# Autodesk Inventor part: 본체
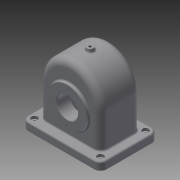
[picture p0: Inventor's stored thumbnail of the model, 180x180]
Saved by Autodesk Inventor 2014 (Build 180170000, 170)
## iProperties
Created: 2016-10
Part Number: 본체
Material: 일반
Document SubType Name: Modeling
Designer: USER
Density: 1 g/cm^3
Appearance: 기본값
Author: USER
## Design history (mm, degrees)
sketch "스케치1"
  geometry: L1 (0, 0)-(0, 15); L2 (0, 15)-(-150, 15); L3 (-150, 15)-(-150, 0); L4 (-150, 0)-(0, 0)
  constraints: 8 end point, 2 parallel, 1 perpendicular, 1 vertical
  dimensions: "d0" = 15 distance of L1.start L1.end; "d1" = 150 distance of L1.end L2.end
extrude "돌출1" new body sketch "스케치1" stored distance "d2" = 110; taper "d3" = 0 deg
sketch "스케치2"
  geometry: L1 (0, 0)-(-150, 0) reference; L2 (-150, 0)-(-150, 15) reference; L3 (-150, 15)-(0, 15) reference; L4 (0, 15)-(0, 0) reference; L5 (-75, 0)-(-75, 80); L6 (-17, 80)-(-17, 15); L7 (-133, 80)-(-133, 15); A1 r 58 centre (-75, 80) between (-17, 80) and (-133, 80)
  constraints: 6 end point, 2 perpendicular, 2 point on circle, 2 point on line, 2 tangent, 1 centre point, 1 coincident, 1 midpoint, 1 parallel
  dimensions: "d4" = 80 distance of L5.start L5.end; "d5" = 116 diameter of A1
extrude "돌출2" join sketch "스케치2" stored distance "d6" = 77; taper "d7" = 0 deg
sketch "스케치3"
  geometry: L1 (0, 0)-(-150, 0) reference; L2 (-150, 0)-(-150, 15) reference; L3 (-150, 15)-(-133, 15) reference; L4 (-133, 15)-(-133, 80) reference; L5 (-17, 80)-(-17, 15) reference; L6 (-17, 15)-(0, 15) reference; L7 (0, 15)-(0, 0) reference; L8 (-75, 0)-(-75, 65); C1 r 20 at (-75, 65); A1 r 58 centre (-75, 80) between (-17, 80) and (-133, 80) reference
  constraints: 2 end point, 1 centre point, 1 coincident, 1 midpoint, 1 parallel
  dimensions: "d8" = 65 distance of L8.start L8.end; "d9" = 40 diameter of C1
extrude "돌출3" cut sketch "스케치3" stored distance "d10" = 100; taper "d11" = 0 deg
sketch "스케치4"
  geometry: C1 r 20 at (75, 65) reference; C2 r 37.5 at (75, 65); 1 further point
  constraints: 1 centre point, 1 coincident
  dimensions: "d12" = 75 diameter of C2
extrude "돌출4" join sketch "스케치4" distance "d13" = 5; taper "d14" = 0 deg
sketch "스케치5"
  geometry: C1 r 20 at (75, -65) reference; C2 r 31 at (75, -65); 1 further point
  constraints: 1 centre point, 1 coincident
  dimensions: "d15" = 62 diameter of C2
extrude "돌출5" join sketch "스케치5" distance "d16" = 10; taper "d17" = 0 deg
sketch "스케치6"
  geometry: L1 (0, 0)-(-150, 0) reference; L2 (-150, 0)-(-150, 15) reference; L3 (-150, 15)-(-133, 15) reference; L4 (-133, 15)-(-133, 80) reference; L5 (-17, 80)-(-17, 15) reference; L6 (-17, 15)-(0, 15) reference; L7 (0, 15)-(0, 0) reference; L8 (-23, 80)-(-23, 0); L9 (-127, 80)-(-127, 0); C1 r 20 at (-75, 65) reference; A1 r 58 centre (-75, 80) between (-17, 80) and (-133, 80) reference; A2 r 52 centre (-75, 80) between (-23, 80) and (-127, 80)
  constraints: 4 end point, 2 point on circle, 2 point on line, 2 tangent, 1 centre point, 1 coincident, 1 parallel, 1 perpendicular
  dimensions: "d18" = 104 diameter of A2
extrude "돌출6" cut sketch "스케치6" stored distance "d19" = 67; taper "d20" = 0 deg
node "작업 평면1"
sketch "스케치7"
  geometry: L1 (-19, 87)-(-19, 77) reference; L2 (-19, 77)-(0, 77) reference; L3 (0, 77)-(0, 93.5) reference; L4 (0, 93.5)-(15, 93.5) reference; L5 (15, 93.5)-(15, 72) reference; L6 (15, 72)-(-30, 72) reference; L7 (-30, 72)-(-30, 87) reference; L8 (-30, 87)-(-19, 87) reference; L9 (-123, 0)-(-123, 77) reference; L10 (-123, 77)-(-81, 77) reference; L11 (-81, 77)-(-81, 87) reference; L12 (-81, 87)-(-70, 87) reference; L13 (-70, 87)-(-70, 72) reference; L14 (-70, 72)-(-117, 72) reference; L15 (-117, 72)-(-117, 5) reference; L16 (-117, 5)-(-70, 5) reference; L17 (-70, 5)-(-70, -5) reference; L18 (-70, -5)-(-87.5, -5) reference; L19 (-87.5, -5)-(-87.5, 0) reference; L20 (-87.5, 0)-(-123, 0) reference; L21 (15, -16.5)-(0, -16.5) reference; L22 (0, -16.5)-(0, 0) reference; L23 (0, 0)-(-12.5, 0) reference; L24 (-12.5, 0)-(-12.5, -5) reference; L25 (-12.5, -5)-(-30, -5) reference; L26 (-30, -5)-(-30, 5) reference; L27 (-30, 5)-(15, 5) reference; L28 (15, 5)-(15, -16.5) reference; L29 (-70, -5)-(-30, -5); L30 (-50, -5)-(-50, 38.5); L31 (-50, -5)-(-50, 19); L32 (-50, 19)-(-78, 19); L33 (-78, 19)-(-89.747, 5); L34 (-70, 5)-(-50, 5); 1 further point
  constraints: 12 end point, 3 perpendicular, 3 point on line, 1 collinear, 1 midpoint
  dimensions: "d21" = 24 distance of L30.start L31.end; "d22" = 28 distance of L31.end L32.end; "d23" = 50 deg angle of L33 L32
revolve "회전1" sketch "스케치7" stored, may be unused: angle "d24" = 90 deg
sketch "스케치8"
  geometry: C1 r 20 at (0, 0) reference; 1 further point
extrude "돌출7" cut sketch "스케치8" distance "d25" = 100; taper "d26" = 0 deg
sketch "스케치9"
  geometry: C1 r 37.5 at (0, 0) reference; A1 r 29 centre (0, 0) between (-29, 0) and (0, 29); 3 further points
  constraints: 4 point on circle, 1 centre point, 1 coincident
  dimensions: "d27" = 58 diameter of A1
hole "구멍1" sketch "스케치9" at (-29, 0), (0, 29), (29, 0), (0, -29) diameter "d28" = 2.459; stored, may be unused: countersink angle "d32" = 90 deg, drill point angle "d34" = 118 deg; dims "d29" = 6, "d30" = 4, "d31" = 2, "d33" = 8
sketch "스케치10"
  geometry: C1 r 31 at (0, 0) reference; A1 r 26 centre (0, 0) between (26, 0) and (0, 26); 3 further points
  constraints: 4 point on circle, 1 centre point, 1 coincident
  dimensions: "d35" = 52 diameter of A1
hole "구멍2" sketch "스케치10" at (26, 0), (0, 26), (-26, 0), (0, -26) diameter "d36" = 2.459; stored, may be unused: countersink angle "d40" = 90 deg, drill point angle "d42" = 118 deg; dims "d37" = 6, "d38" = 4, "d39" = 2, "d41" = 8
fillet "모깎기1" dims "d43" = 13
fillet "모깎기2" dims "d44" = 8
fillet "모깎기3" dims "d45" = 12
sketch "스케치11"
  geometry: A1 r 12 centre (0, 98) between (0, 110) and (-12, 98) reference; A2 r 12 centre (0, 12) between (-12, 12) and (0, 0) reference; A3 r 12 centre (126, 12) between (126, 0) and (138, 12) reference; A4 r 12 centre (126, 98) between (138, 98) and (126, 110) reference; 1 further point
hole "구멍3" sketch "스케치11" at (0, 98), (0, 12), (126, 98), (126, 12) diameter "d46" = 5; stored, may be unused: countersink angle "d50" = 90 deg, drill point angle "d52" = 118 deg; dims "d47" = 6, "d48" = 12, "d49" = 5, "d51" = 20
fillet "모깎기4" dims "d53" = 3
sketch "스케치12"
  geometry: L1 (-127, 80)-(-127, 0) reference; L2 (-127, 0)-(-150, 0) reference; L3 (-150, 0)-(-150, 12) reference; L4 (-147, 15)-(-136, 15) reference; L5 (-133, 18)-(-133, 80) reference; L6 (-17, 80)-(-17, 18) reference; L7 (-14, 15)-(-3, 15) reference; L8 (0, 12)-(0, 0) reference; L9 (0, 0)-(-23, 0) reference; L10 (-23, 0)-(-23, 80) reference; L11 (-23, 0)-(-127, 0); L12 (-75, 144)-(-81, 144); L13 (-81, 144)-(-82.136, 137.559); L14 (-75, 0)-(-75, 132); L15 (-75, 138)-(-75, 144); A1 r 52 centre (-75, 80) between (-23, 80) and (-127, 80) reference; A2 r 3 centre (-147, 12) between (-147, 15) and (-150, 12) reference; A3 r 3 centre (-136, 18) between (-136, 15) and (-133, 18) reference; A4 r 58 centre (-75, 80) between (-17, 80) and (-133, 80) reference; A5 r 3 centre (-14, 18) between (-17, 18) and (-14, 15) reference; A6 r 3 centre (-3, 12) between (0, 12) and (-3, 15) reference
  constraints: 10 end point, 4 perpendicular, 3 point on circle, 1 collinear, 1 midpoint
  dimensions: "d54" = 144 distance of L14.start L12.start; "d55" = 6 distance of L12.start L12.end
revolve "회전2" sketch "스케치12" stored, may be unused: angle "d57" = 90 deg
sketch "스케치13"
  geometry: C1 r 6 at (0, 0) reference; 1 further point
hole "구멍4" sketch "스케치13" at (0, 0) diameter "d58" = 4.459; stored, may be unused: countersink angle "d62" = 90 deg, drill point angle "d64" = 118 deg; dims "d59" = 20, "d60" = 4, "d61" = 2, "d63" = 20
fillet "모깎기5" dims "d65" = 3
chamfer "모따기1" distance "d66" = 1; stored, may be unused: second distance "d67" = 2, angle "d68" = 45 deg
node "솔리드1"
node "절단 모서리 투영1"
node "절단 모서리 투영2"
node "절단 모서리 투영3"
node "절단 모서리 투영4"
node "절단 모서리 투영5"
